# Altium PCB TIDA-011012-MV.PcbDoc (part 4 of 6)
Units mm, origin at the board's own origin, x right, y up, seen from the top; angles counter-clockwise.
Board outline 360 x 280 mm, 4 copper layers (Top Layer, Layer 1, Layer 2, Bottom Layer), stack 2.066 mm thick; 566 components, 345 nets, 1738 pads, 2486 vias.
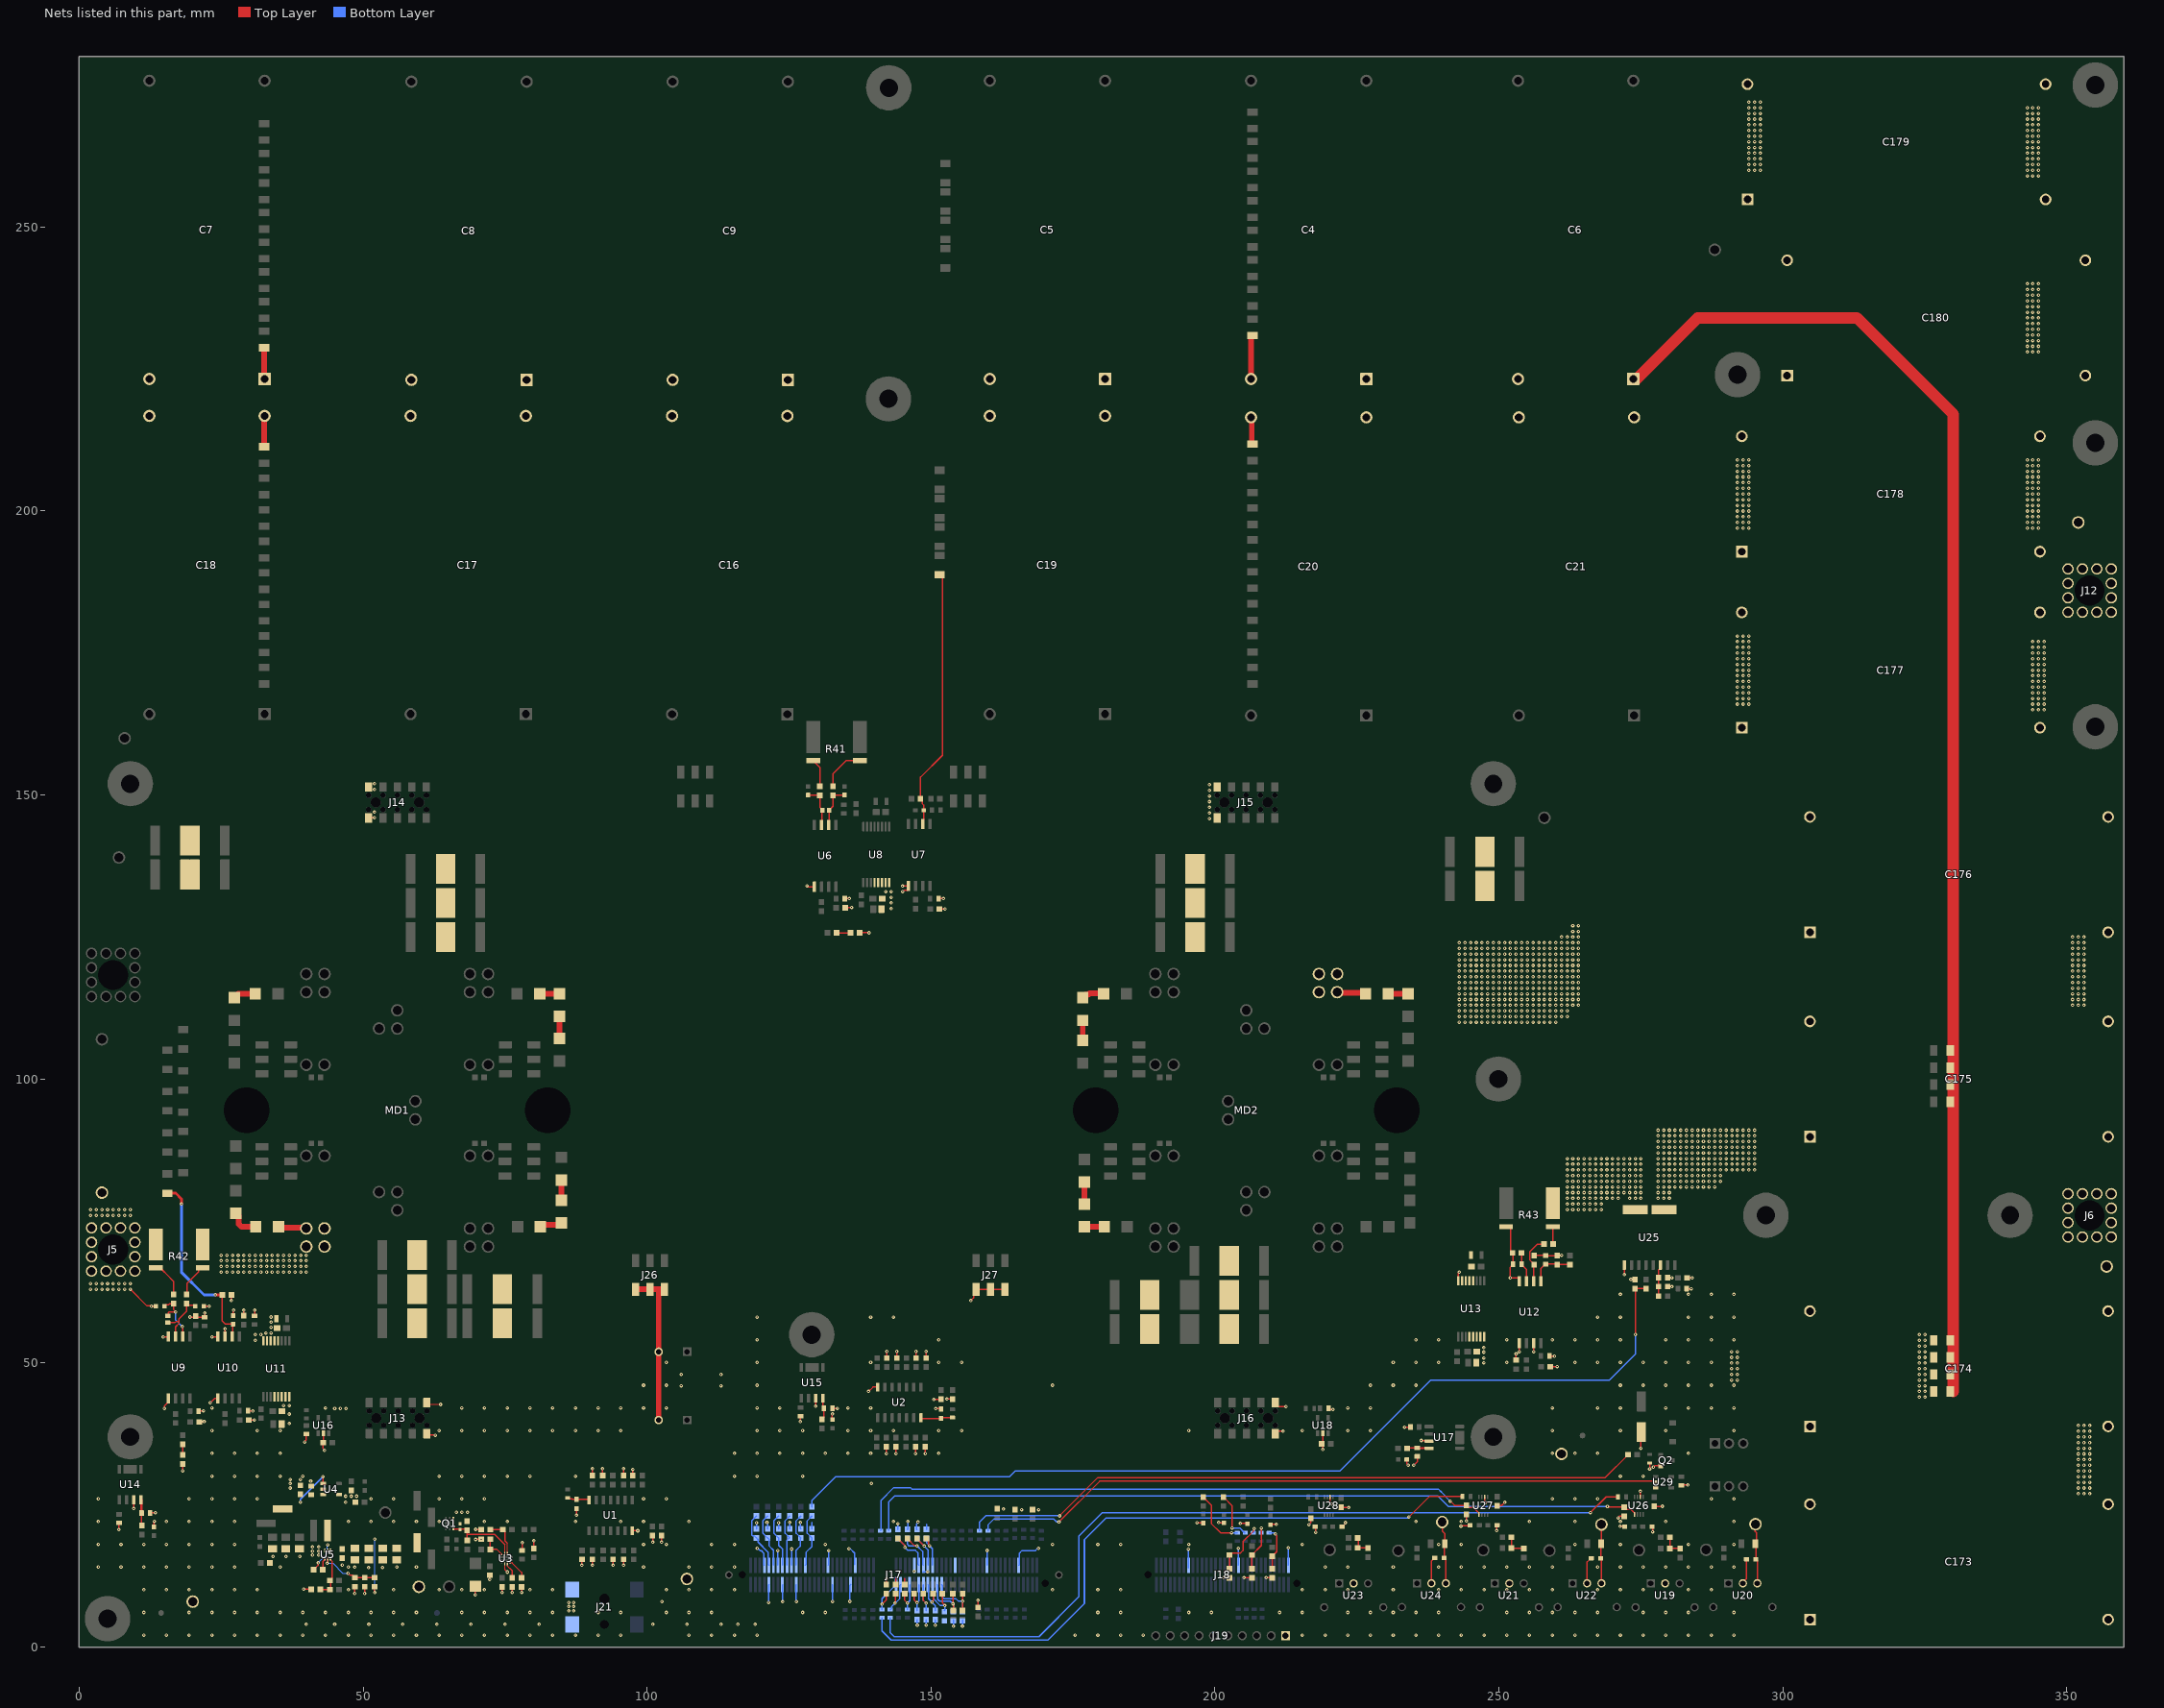
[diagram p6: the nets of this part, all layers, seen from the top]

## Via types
v1: diameter 0.6, hole 0.2, Top Layer to Bottom Layer, tented both sides, 2486 vias

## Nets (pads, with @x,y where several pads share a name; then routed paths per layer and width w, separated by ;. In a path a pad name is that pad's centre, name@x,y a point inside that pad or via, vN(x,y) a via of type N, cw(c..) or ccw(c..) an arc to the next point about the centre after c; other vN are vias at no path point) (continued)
EF_ILIM: R136.2 U3.9 | length 2.7
  Top Layer w0.2: U3.9@75.41,14.499 75.41,14.279 75.823,13.867
  Top Layer w0.254: 75.823,13.867 75.833,13.867 76.246,13.454 R136.2@76.246,12.176
EF_ITIMER: C60.1 U3.10 | length 3.7
  Top Layer w0.254: U3.10@75.86,14.824 76.21,14.824 77.897,13.137 C60.1@77.897,12.176
EF_OVLO: R138.1 R141.2 U3.2 | length 6.8
  Top Layer w0.2: U3.2@75.385,16.474 75.385,18.282
  Top Layer w0.254: R141.2@72.388,20.693 72.398,20.703 74.575,20.703 74.96,20.318 74.96,18.707 75.385,18.282
EF_PG: C62.1 Q1.3 R139.1 R142.2 U3.3 | length 13.2
  Top Layer w0.2: U3.3@74.935,16.474 74.935,18.065
  Top Layer w0.254: Q1.3@65.884,20.784 68.111,20.784 R142.2@68.321,20.574 68.321,19.824 ; R139.1@68.335,18.807 68.321,18.821 68.321,19.824 ; 74.935,18.065 73.176,19.824 68.321,19.824
EF_PGTH: R135.1 R137.2 U3.4 | length 4.2
  Top Layer w0.254: R137.2@72.386,18.961 72.386,17.183 R135.1@72.393,17.176 73.559,17.176 U3.4@74.41,16.324
FAN_EN: R88.1 R187.1 | length 120.7
  Top Layer w0.254: v1(172.619,23.095) 179.372,29.848 268.693,29.848 272.7,33.855 R187.1@272.725,33.855
  Bottom Layer w0.254: R88.1@158.514,20.444 158.514,21.978 159.63,23.095 v1(172.619,23.095)
FAN_PWM: R90.1 U29.2 | length 122.3
  Top Layer w0.254: v1(172.519,22.02) 179.699,29.2 277.07,29.2 277.078,29.192 277.419,29.192 U29.2@277.592,29.019
  Bottom Layer w0.254: R90.1@160.072,20.444 160.072,21.559 161.023,22.51 171.632,22.51 172.123,22.02 v1(172.519,22.02)
FSIRXA_CLK: R71.2 R215.1 | length 147.5
  Top Layer w0.254: v1(266.1,23.68) 268.865,26.445 R215.1@270.956,26.445
  Bottom Layer w0.254: R71.2@142.799,5.144 142.799,2.562 143.52,1.841 168.993,1.841 176,8.848 176,19.5 180.18,23.68 v1(266.1,23.68)
FSIRXA_D0: R69.2 R216.1 | length 122.2
  Top Layer w0.254: v1(234.151,22.915) 237.732,26.495 R216.1@243.555,26.495
  Bottom Layer w0.254: R69.2@141.374,5.144 141.374,2.842 142.973,1.243 143.476,1.243 143.69,1.243 144.647,1.243 170.578,1.243 177,7.665 177,18.917 180.789,22.706 233.879,22.706 234.088,22.915 v1(234.151,22.915)
FSITXA_CLK: C147.1 R72.1 U26.5 | length 138.3
  Top Layer w0.254: v1(269.089,24.735) 269.155,24.735 269.255,24.634 272.032,24.634 272.432,24.234 273.242,24.234 273.881,23.595 U26.5@273.881,23.345
  Bottom Layer w0.254: R72.1@142.521,20.494 142.521,25.519 143.627,26.625 239.186,26.625 241.077,24.735 v1(269.089,24.735)
FSITXA_D0: C149.1 R70.1 U27.5 | length 113.7
  Top Layer w0.254: v1(241.425,25.695) 242.175,24.945 C149.1@244.28,24.945 ; C149.1@244.28,24.92 244.655,24.545 245.531,24.545 246.481,23.595 U27.5@246.481,23.345
  Bottom Layer w0.2: 239.858,27.262 v1(241.425,25.695)
  Bottom Layer w0.254: R70.1@141.077,20.494 141.175,20.592 141.175,25.818 143.357,28 146.454,28 146.658,27.796 220.26,27.796 220.279,27.816 239.304,27.816 239.858,27.262
GND: C10.2 C22.2 C27.2 C28.2 C29.2 C30.2 C31.1 C32.2 C33.2 C34.2 C35.2 C36.1 C37.1 C38.1 C39.1 C40.2 C41.2 C42.1 C43.2 C44.2 C45.1 C46.2 C47.2 C48.2 C49.1 C50.1 C51.1 C52.1 C53.1 C54.2 C55.2 C56.2 C57.2 C59.2 C60.2 C61.2 C62.2 C64.2 C66.2 C67.2 C68.2 C69.2 C70.2 C72.2 C73.2 C74.2 C78.2 C81.2 C82.2 C83.2 C87.2 C88.1 C90.2 C92.2 C93.2 C97.2 C100.2 C101.2 C102.2 C106.2 C107.1 C109.2 C113.2 C114.2 C116.2 C119.1 C121.2 C122.2 C123.2 C124.1 C125.2 C126.2 C127.1 C128.2 C129.2 C130.2 C131.1 C132.2 C133.2 C135.1 C137.1 C138.1 C140.1 C141.1 C142.1 C143.1 C144.1 C145.1 C146.2 C147.2 C148.2 C149.2 C150.2 C151.2 C152.2 C153.2 C154.2 C155.2 C158.1 C159.2 C160.2 C162.2 C169.2 C170.2 C171.1 C172.2 D25.1 D26.1 D27.1 D28.1 D30.2 J13.9 J13.10 J14.9 J14.10 J15.9 J15.10 J16.9 J16.10 J17.7 J17.10 J17.13 J17.16 J17.19 J17.22 J17.35 J17.38 J17.46 J17.47 J17.65 J17.83 J17.97 J17.111 J18.135 J18.157 J18.179 J19.1 J21.2 J21.3 J26.2 J26.4 J26.6 J27.2 J27.4 J27.6 Q1.4 Q1.7 Q2.2 R53.1 R54.1 R55.1 R89.1 R91.1 R92.1 R93.1 R120.1 R121.1 R122.1 R123.1 R136.1 R137.1 R141.1 R142.1 R145.2 R146.1 R147.1 R148.1 R188.1 R190.1 R192.1 R200.1 R201.1 R203.2 R204.1 R205.1 R206.1 R207.1 TP2.1 TP21.1 TP22.1 TP23.1 U1.7 U2.7 U3.8 U4.2 U4.4 U5.3 U6.5 U7.5 U8.4 U8.5 U8.6 U8.7 U8.8 U9.5 U10.5 U11.4 U11.5 U11.6 U11.7 U11.8 U12.5 U12.7 U13.4 U13.5 U13.6 U13.7 U13.8 U14.3 U15.3 U16.2 U17.3 U18.2 U19.2 U20.2 U21.2 U22.2 U23.2 U24.2 U25.3 U26.2 U27.2 U28.2 U29.3 | length 261
  Top Layer w0.2: J13.9@61.23,43.02 61.23,42.866 61.385,42.711 v1(63.623,42.711) ; 74.935,13.665 U3.8@74.935,14.674
  Top Layer w0.254: v1(7.002,20.681) 7.002,21.843 C123.2@7.005,21.847 ; v1(9.61,24.378) 9.615,24.383 9.615,25.911 U14.3@9.62,25.916 ; C125.2@12.504,23.59 12.554,23.64 v1(13.416,23.64) ; C124.1@13.166,21.14 13.191,21.165 13.191,22.115 v1(13.216,22.14) ; v1(15,42) 15.057,42.057 15.057,42.512 15.695,43.15 U9.5@15.695,43.75 ; v1(18.235,31.021) C100.2@18.235,32.2 ; C92.2@21.051,41.547 21.101,41.597 v1(21.894,41.597) ; C93.2@21.144,39.653 21.982,39.653 v1(22,39.671) ; v1(23.075,43) 23.825,43.75 U10.5@24.395,43.75 ; C101.2@29.735,41.637 29.825,41.547 v1(30.58,41.547) ; C102.2@29.83,39.949 29.881,40 v1(30.86,40) ; R147.1@33.602,14.815 R147.1@33.64,14.852 ; v1(39.506,10.198) 40.794,10.198 R146.1@40.844,10.148 ; v1(39.7,36.1) 39.7,36.194 40,36.494 C129.2@40,37.49 ; U16.2@43,37.625 43,36.046 R190.1@42.954,36 42.954,34.949 43.204,34.699 v1(43.204,34.632) ; v1(48.529,9.423) 48.529,10.605 C172.2@48.548,10.623 ; v1(50.248,9.423) 50.248,10.596 R145.2@50.275,10.623 ; J14.9@50.97,146.18 51.15,146 51.9,146 v1@52,145.9 ; J14.10@50.97,151.62 J14.10@51,151.65 ; J13.10@61.23,37.38 62.536,37.38 62.633,37.283 v1(62.7,37.283) ; Q1.7@65.884,21.854 Q1.4@65.884,22.734 ; D30.2@69.748,10.716 69.77,10.694 v1(69.77,9.191) ; v1(69.832,18.95) 70.774,18.95 v1(70.786,18.961) R137.1@70.761,18.961 ; v1(69.85,20.722) 70.759,20.722 R141.1@70.788,20.693 ; v1(72.303,11.893) C59.2@72.303,12.643 ; v1(74.46,9.62) C61.2@74.46,10.561 ; 74.935,13.665 v1(75.4,13.2) ; v1(76.246,9.62) R136.1@76.246,10.576 ; v1(77.897,9.626) C60.2@77.897,10.576 ; C10.2@78,17 v1(78,18.38) ; C57.2@80.071,17.374 v1(80.071,18.709) ; v1(87.546,23.184) C31.1@87.546,24.359 ; v1(88.501,14.394) 88.501,15.389 R91.1@88.546,15.434 ; v1(90.392,14.394) C37.1@90.392,15.434 ; R93.1@90.392,30.209 v1(90.392,31.386) ; v1(92.158,31.386) 92.158,30.227 C39.1@92.176,30.209 ; v1(94.021,14.394) R89.1@94.021,15.434 ; v1(95.826,31.386) 95.826,30.201 C38.1@95.842,30.184 ; C36.1@95.844,15.434 95.861,15.417 v1(95.861,14.394) ; U1.7@97.356,20.484 97.366,20.475 v1(98.355,20.475) ; R92.1@97.489,30.184 v1(97.489,31.285) ; C42.1@100.962,19.632 101,19.594 v1(101,18.45) ; v1(102.546,18.45) R204.1@102.546,19.632 ; v1(126.98,39.691) 126.98,40.625 C126.2@127,40.645 ; v1(128.141,134.013) 128.208,134.013 128.358,133.863 U6.5@129.461,133.863 ; v1(129.67,42.384) 129.68,42.395 129.68,44.231 U15.3@129.691,44.241 ; v1@132.604,41.056 v1(132.614,41.045) 132.604,41.035 132.604,40.056 C127.1@132.614,40.045 ; C128.2@132.637,42.022 v1(133.513,42.022) ; C73.2@134.799,131.764 v1(135.597,131.764) ; C74.2@134.894,130.142 134.969,130.217 v1(136,130.217) ; C81.2@137.406,125.741 137.416,125.752 v1(139.079,125.752) ; v1(139,45) 139.775,45.775 U2.7@140.622,45.775 ; C153.2@142.114,11.001 142.128,11.015 v1(142.128,11.956) ; C51.1@142.117,35.275 142.136,35.256 v1(142.136,34.052) ; C49.1@142.233,50.875 v1(142.233,52.047) ; C154.2@143.764,11.016 143.771,11.022 143.771,12.052 ; v1(143.835,34.052) R122.1@143.835,35.275 ; R120.1@143.951,50.875 143.96,50.884 v1(143.96,52.047) ; v1(144.971,133.96) 145.943,133.96 145.943,133.369 145.823,133.248 145.315,133.248 145.067,133 v1(145,133) ; 145.368,12.046 145.368,10.982 C155.2@145.371,10.98 ; v1(147.247,34.052) 147.247,35.251 C52.1@147.271,35.275 ; v1(147.336,52.047) 147.336,50.926 C50.1@147.387,50.875 ; v1(148.989,34.052) R123.1@148.989,35.275 ; R121.1@149.105,50.875 v1(149.105,52.047) ; v1(150.455,43.583) 151.698,43.583 C53.1@151.773,43.658 ; v1(150.827,41.975) 151.698,41.975 C45.1@151.773,41.9 ; C82.2@151.351,131.764 v1(152.196,131.764) ; C83.2@151.446,129.933 v1(152.461,129.933) ; v1(152.788,43.658) R205.1@153.763,43.658 ; v1(157,61) 157.476,61.476 157.476,62.491 J27.2@157.96,62.975 J27.4@160.5,62.975 J27.6@163.04,62.975 ; C106.2@158.247,6.99 v1(158.247,8.222) ; v1(196.818,21.89) 197.854,21.89 D26.1@197.929,21.815 ; v1(200.648,21.915) 200.673,21.89 201.535,21.89 D25.1@201.56,21.865 ; v1(201.486,12.194) R55.1@202.541,12.194 ; v1(204.474,21.746) 205.682,21.746 D28.1@205.713,21.715 ; v1(205.098,12.191) 206.499,12.191 R54.1@206.502,12.194 ; v1(209.011,12.228) 209.8,12.228 R53.1@210.07,11.958 ; D27.1@209.753,21.546 209.803,21.596 v1(210.815,21.596) ; J16.10@210.63,37.38 210.63,37.492 211.138,38 v1(212,38) ; J16.9@210.63,42.82 211.099,42.351 212.484,42.351 v1(212.491,42.345) ; v1(216.544,21.546) 216.544,21.56 216.849,21.865 C151.2@216.849,22.665 ; C145.1@217.629,21.22 217.719,21.13 v1(217.719,20.196) ; v1(218.978,34.777) 218.978,35.971 219,35.993 U18.2@219,37.625 ; C133.2@220,42 220.175,41.825 v1(220.764,41.825) ; U28.2@220.269,26.419 220.269,25.539 220.5,25.308 v1(220.5,25.2) ; C152.2@222.221,24.61 222.285,24.545 v1(223.528,24.545) ; C137.1@222.374,21.215 222.437,21.215 222.88,21.658 222.88,21.85 v1(222.937,21.908) ; v1(233.391,38.728) 234.39,38.728 C130.2@234.417,38.755 ; C131.1@233.75,33 233.775,32.975 233.775,32.262 234,32.037 v1(234,32) ; v1(235,32) 235.616,32.616 C132.2@235.616,33.567 ; v1(236.302,36.366) 236.346,36.322 237.639,36.322 U17.3@237.683,36.278 ; U24.2@238.101,11.226 238.101,15.139 238.638,15.675 C140.1@238.701,15.675 ; v1(243.3,21.3) 243.366,21.366 244.783,21.366 C143.1@244.892,21.475 ; v1(244.28,22.213) C149.2@244.28,23.345 ; U27.2@247.481,26.445 247.481,25.6 247.615,25.466 v1(247.615,25.384) ; v1(249.599,20.49) 249.599,21.399 C144.1@249.674,21.475 ; C150.2@249.674,24.895 250.437,24.895 v1(251.007,25.466) ; C116.2@253.017,50.528 v1(253.017,51.6) ; v1(253.56,52) U12.5@253.56,53.5 ; v1(256.1,52) U12.7@256.1,53.5 ; C113.2@258.88,51.228 258.908,51.2 v1(259.774,51.2) ; C114.2@259.024,49.38 v1(260.249,49.38) ; U22.2@265.52,11.226 265.52,14.978 266.192,15.65 C138.1@266.256,15.65 ; v1(270.956,22.728) 271.262,23.034 C147.2@272.057,23.034 ; v1(271.303,21.257) 272.085,21.257 C141.1@272.131,21.21 ; v1@272,65.504 v1(272.055,65.559) U25.3@272.055,67.247 ; v1(273.235,64.725) C160.2@273.96,64.725 ; U26.2@274.881,26.445 v1(274.881,27.417) ; v1(275,35) 275,37.751 C122.2@275.075,37.826 ; v1(276.53,31.355) R188.1@276.53,32.38 ; C142.1@276.971,21.219 277.045,21.144 v1(277.045,20.282) ; v1(277.192,31.685) 277.412,31.905 Q2.2@278.471,31.905 ; C148.2@277.363,24.768 277.377,24.782 v1(278.75,24.782) ; R203.2@279.695,63.45 v1(280.445,63.45) ; C162.2@279.695,65.029 v1(280.445,65.029) ; C146.2@282.138,28.45 282.207,28.519 v1(283.288,28.519) ; C158.1@283.042,63.125 283.097,63.069 v1(283.842,63.069) ; C159.2@283.092,65 v1(284,65) ; U20.2@292.939,11.226 292.939,11.388 293.583,12.032 C135.1@293.583,15.475
  Top Layer w1: J26.2@97.96,62.975 J26.4@100.5,62.975 102,62.975 ; C56.2@102.037,39.966 102.037,62.938 102,62.975 ; J26.6@103.04,62.975 102,62.975
  Bottom Layer w0.254: C27.2@119.25,20.8 v1(119.25,21.855) ; v1(119.4,17.4) 119.469,17.4 119.916,16.953 120.125,16.953 120.524,16.554 120.524,14.517 J17.7@120.647,14.394 ; v1(121.103,21.918) 121.103,21.852 121.2,21.755 C28.2@121.2,20.8 ; v1(121.408,7.865) 121.428,7.884 121.428,10.975 J17.10@121.447,10.994 ; v1(123,17) 123.047,16.953 J17.13@123.047,14.394 ; C29.2@123.15,20.8 v1(123.15,21.852) ; J17.16@123.847,10.994 123.867,10.974 123.867,7.981 v1(123.887,7.962) ; C32.2@125.1,20.8 v1(125.1,21.918) ; J17.19@125.447,14.394 v1(125.447,17.26) ; J17.22@126.247,10.994 126.258,10.983 126.258,8.021 v1(126.268,8.01) ; v1(127,21.918) 127,20.85 C34.2@127.05,20.8 ; C40.2@129,20.8 129,21.918 ; J17.35@131.847,14.394 131.953,14.5 131.953,16.953 v1(132,17) ; v1(132.633,8.019) 132.64,8.026 132.64,10.987 J17.38@132.647,10.994 ; v1(135.547,17.307) 135.594,17.26 135.817,17.26 136.524,16.554 J17.47@136.524,14.517 ; v1(135.684,8.039) 135.731,8.086 135.731,10.864 135.724,10.871 J17.46@135.847,10.994 J17.46@135.832,11.009 ; C44.2@144.164,20.698 v1(144.164,21.721) ; C47.2@145.836,20.698 145.9,20.762 v1(145.9,22.1) ; v1(147.032,13.321) J17.65@147.04,13.329 ; C48.2@147.508,20.698 147.461,20.744 147.461,21.667 147.7,21.906 v1(147.7,22) ; C30.2@147.522,4.821 147.572,4.771 v1(147.572,3.867) ; 148.561,13.264 v1(149.416,13.264) ; v1(149.122,3.867) C33.2@149.122,4.821 ; C54.2@149.18,20.698 149.18,21.648 ; v1(150.722,3.867) C35.2@150.722,4.821 ; v1@153.922,3.867 C43.2@153.922,4.821 ; v1@155.522,3.867 C46.2@155.522,4.821 ; J17.97@159.847,14.394 v1(159.847,17.007) ; J17.111@165.455,14.386 J17.111@165.447,14.394 165.57,14.517 165.57,16.554 165.997,16.98 168.387,16.98 168.806,17.4 v1(168.9,17.4) ; J18.135@195.311,13.885 v1(195.311,17.24) 195.313,17.238 195.313,14.396 J18.135@195.315,14.394 ; v1(204.097,17.375) 204.106,17.366 204.106,14.403 J18.157@204.115,14.394 ; v1(212.902,17.469) 212.909,17.463 212.909,14.401 J18.179@212.915,14.394
  other v1: 11.371,2.096 15.371,2.096 19.37,2.096 23.37,2.096 27.37,2.096 31.37,2.096 35.37,2.096 39.37,2.096 43.37,2.096 47.37,2.096 51.37,2.096 55.37,2.096 59.37,2.096 63.37,2.096 67.37,2.096 71.37,2.096 75.37,2.096 79.37,2.096 83.37,2.096 87.37,2.096 91.37,2.096 95.37,2.096 107.37,2.096 111.37,2.096 115.37,2.096 119.37,2.096 175.37,2.096 179.37,2.096 183.37,2.096 187.37,2.096 215.37,2.096 219.37,2.096 223.37,2.096 227.37,2.096 231.37,2.096 235.37,2.096 239.37,2.096 243.37,2.096 247.37,2.096 251.37,2.096 255.37,2.096 259.37,2.096 263.37,2.096 267.37,2.096 271.37,2.096 275.37,2.096 279.37,2.096 283.37,2.096 287.37,2.096 291.37,2.096 153.922,3.667 155.522,3.667 40,4 45,4 51,4 57,4 63,4 69,4 75,4 81,4 101,4 107,4 113,4 116,4 119,4 11.371,6.096 19.37,6.096 23.37,6.096 27.37,6.096 31.37,6.096 35.37,6.096 39.37,6.096 43.37,6.096 47.37,6.096 51.37,6.096 55.37,6.096 59.37,6.096 67.37,6.096 71.37,6.096 75.37,6.096 79.37,6.096 83.37,6.096 91.37,6.096 95.37,6.096 103.37,6.096 107.37,6.096 111.37,6.096 127.37,6.096 131.37,6.096 179.37,6.096 183.37,6.096 195.37,6.096 199.37,6.096 211.37,6.096 215.37,6.096 223.37,6.096 227.37,6.096 231.37,6.096 235.37,6.096 239.37,6.096 251.37,6.096 255.37,6.096 259.37,6.096 263.37,6.096 267.37,6.096 275.37,6.096 279.37,6.096 283.37,6.096 291.37,6.096 86.205,6.364 87.046,6.364 86.201,7.123 87.046,7.123 86.201,7.839 87.046,7.839 102.6,8 11.371,10.096 15.371,10.096 19.37,10.096 23.37,10.096 27.37,10.096 31.37,10.096 47.37,10.096 55.37,10.096 63.37,10.096 67.37,10.096 71.37,10.096 79.37,10.096 83.37,10.096 103.37,10.096 107.37,10.096 111.37,10.096 115.37,10.096 171.37,10.096 179.37,10.096 183.37,10.096 215.37,10.096 219.37,10.096 223.37,10.096 231.37,10.096 239.37,10.096 243.37,10.096 247.37,10.096 251.37,10.096 255.37,10.096 259.37,10.096 267.37,10.096 271.37,10.096 275.37,10.096 283.37,10.096 287.37,10.096 50.925,13.982 53.421,14.009 48.529,14.051 55.928,14.073 3.371,14.096 7.371,14.096 11.371,14.096 15.371,14.096 19.37,14.096 23.37,14.096 27.37,14.096 35.37,14.096 47.37,14.096 59.37,14.096 99.37,14.096 107.37,14.096 111.37,14.096 115.37,14.096 219.37,14.096 223.37,14.096 231.37,14.096 239.37,14.096 243.37,14.096 247.37,14.096 251.37,14.096 255.37,14.096 259.37,14.096 267.37,14.096 271.37,14.096 275.37,14.096 279.37,14.096 283.37,14.096 287.37,14.096 291.37,14.096 46.342,14.42 34.121,15.932 36.412,15.939 38.845,15.961 41.094,16.2 42.194,16.2 41.094,16.886 42.194,16.886 41.094,17.603 42.194,17.603 3.371,18.096 7.371,18.096 11.371,18.096 15.371,18.096 19.37,18.096 23.37,18.096 27.37,18.096 99.37,18.096 103.37,18.096 111.37,18.096 115.37,18.096 131.37,18.096 171.37,18.096 179.37,18.096 183.37,18.096 195.37,18.096 215.37,18.096 239.37,18.096 243.37,18.096 263.37,18.096 271.37,18.096 283.37,18.096 291.37,18.096 3.371,22.096 15.371,22.096 19.37,22.096 23.37,22.096 27.37,22.096 47.37,22.096 51.37,22.096 55.37,22.096 59.37,22.096 63.37,22.096 71.37,22.096 75.37,22.096 87.37,22.096 95.37,22.096 99.37,22.096 107.37,22.096 143.37,22.096 235.37,22.096 243.37,22.096 255.37,22.096 263.37,22.096 271.37,22.096 279.37,22.096 291.37,22.096 66.414,23.716 67.384,23.716 68.366,23.716 165.947,24.185 168.947,24.185 162.713,24.296 46.923,25.501 3.371,26.096 19.37,26.096 23.37,26.096 27.37,26.096 31.37,26.096 51.37,26.096 55.37,26.096 63.37,26.096 67.37,26.096 71.37,26.096 99.37,26.096 103.37,26.096 259.37,26.096 263.37,26.096 267.37,26.096 287.37,26.096 291.37,26.096 46.921,26.556 47.895,26.556 48.859,26.556 37.153,28 37.153,28.765 139.5,28.8 40.769,29.186 37.153,29.496 38.943,29.496 23.37,30.096 27.37,30.096 31.37,30.096 35.37,30.096 39.37,30.096 63.37,30.096 67.37,30.096 71.37,30.096 75.37,30.096 79.37,30.096 87.37,30.096 115.37,30.096 119.37,30.096 127.37,30.096 271.37,30.096 275.37,30.096 23.37,34.096 27.37,34.096 31.37,34.096 35.37,34.096 115.37,34.096 119.37,34.096 123.37,34.096 127.37,34.096 131.37,34.096 135.37,34.096 139.37,34.096 151.37,34.096 259.37,34.096 263.37,34.096 267.37,34.096 283.37,34.096 23.37,38.096 31.37,38.096 35.37,38.096 63.37,38.096 67.37,38.096 71.37,38.096 75.37,38.096 79.37,38.096 83.37,38.096 87.37,38.096 91.37,38.096 95.37,38.096 119.37,38.096 123.37,38.096 127.37,38.096 135.37,38.096 139.37,38.096 143.37,38.096 151.37,38.096 155.37,38.096 195.37,38.096 215.37,38.096 223.37,38.096 227.37,38.096 259.37,38.096 271.37,38.096 279.37,38.096 291.37,38.096 36.975,39.346 36.975,41.021 45,42 46,42 47,42 23.37,42.096 43.37,42.096 67.37,42.096 71.37,42.096 75.37,42.096 79.37,42.096 83.37,42.096 87.37,42.096 91.37,42.096 95.37,42.096 99.37,42.096 103.37,42.096 119.37,42.096 123.37,42.096 135.37,42.096 139.37,42.096 223.37,42.096 227.37,42.096 259.37,42.096 267.37,42.096 271.37,42.096 279.37,42.096 283.37,42.096 287.37,42.096 291.37,42.096 36,42.534 36.975,42.534 324,44 325,44 324,45 325,45 106,46 113,46 324,46 325,46 99.37,46.096 103.37,46.096 119.37,46.096 171.37,46.096 227.37,46.096 231.37,46.096 235.37,46.096 271.37,46.096 275.37,46.096 279.37,46.096 283.37,46.096 287.37,46.096 291.37,46.096 290.954,47 291.954,47 324,47 325,47 106,48 113,48 290.954,48 291.954,48 324,48 325,48 290.954,49 291.954,49 324,49 325,49 290.954,50 291.954,50 324,50 325,50 247.34,50.055 103.37,50.096 119.37,50.096 139.37,50.096 151.37,50.096 155.37,50.096 231.37,50.096 235.37,50.096 239.37,50.096 251.37,50.096 263.37,50.096 267.37,50.096 271.37,50.096 275.37,50.096 279.37,50.096 283.37,50.096 287.37,50.096 247.34,50.893 290.954,51 291.954,51 324,51 325,51 247.34,51.928 290.954,52 291.954,52 324,52 325,52 247.34,52.707 324,53 325,53 324,54 325,54 119.37,54.096 151.37,54.096 235.37,54.096 239.37,54.096 251.37,54.096 259.37,54.096 263.37,54.096 267.37,54.096 271.37,54.096 279.37,54.096 283.37,54.096 287.37,54.096 291.37,54.096 324,55 325,55 119.37,58.096 139.37,58.096 143.37,58.096 267.37,58.096 271.37,58.096 283.37,58.096 287.37,58.096 291.37,58.096 271.37,62.096 283.37,62.096 287.37,62.096 291.37,62.096 143,130 143,131 143,132 142,133 143,133 199,145.834 52,146 199,146.834 52,147 199,147.834 199,148.834 199,149.834 199,150.834 52,151 199,151.834 52,152
GND_ISO_AC_SENS: C94.2 C95.2 C98.1 C99.1 C103.2 C104.2 C105.1 C108.1 C110.2 J5.1 R42.2 R179.1 TP15.1 U9.4 U10.3 U10.4 U11.12 U11.13 U11.14 U11.15 U11.16 | length 17.4
  Top Layer w0.254: v1(9,63) 11.948,60.052 12.648,60.052 v1(12.7,60) C98.1@13.5,60 ; v1(14.8,54.6) 15.645,54.6 U9.4@15.695,54.65 ; v1(19.5,58.1) 20.306,58.1 20.402,58.196 20.542,58.055 C94.2@22.1,58.055 v1(22.1,58.8) ; C99.1@21.95,60 v1(22.9,60) ; v1(23.4,54.6) 24.345,54.6 U10.4@24.395,54.65 ; U10.3@25.665,54.65 25.682,54.668 25.682,55.982 v1(25.7,56) ; v1(26.8,61) R179.1@26.8,62 ; C105.1@27.1,58.35 27.15,58.4 27.15,59.25 v1(27.2,59.3) ; C104.2@28.98,58.346 29,58.366 v1(29,59.3) ; C103.2@30.86,58.301 30.9,58.341 v1(30.9,59.3)
  other v1: 31,54 31,55 32,55 32.9,55.3 33.8,55.3 33.8,56.3 33.8,57.2 33.8,58.1 2,63 3,63 4,63 5,63 6,63 7,63 8,63 2,64 3,64 4,64 5,64 6,64 7,64 8,64 9,64 2,76 3,76 4,76 5,76 6,76 7,76 8,76 9,76 2,77 3,77 4,77 5,77 6,77 7,77 8,77 9,77
I_DC_MINUS: R41.4 R152.1 | length 5
  Top Layer w0.254: R41.4@129.231,156.068 130.446,154.853 130.446,151.595 R152.1@130.413,151.563
I_DC_POS: R41.3 R151.1 | length 7.9
  Top Layer w0.254: R151.1@132.731,151.563 132.731,153.731 135.068,156.068 R41.3@137.481,156.068
I_HALL: C160.1 R85.1 R199.2 | length 170.3
  Top Layer w0.254: v1(274,55) 274,63.085 C160.1@273.96,63.125 R199.2@275.865,63.125
  Bottom Layer w0.254: R85.1@129,24.67 129,25.818 133.182,30 163.799,30 164.799,31 222,31 238,47 269.458,47 274,51.542 v1(274,55)
I_HALL_N: R43.1 U25.2
  other v1: 262,77 263,77 264,77 265,77 266,77 267,77 268,77 262,78 263,78 264,78 265,78 266,78 267,78 268,78 262,79 263,79 264,79 265,79 266,79 267,79 268,79 269,79 270,79 271,79 273,79 274,79 275,79 262,80 263,80 264,80 265,80 266,80 267,80 268,80 269,80 270,80 271,80 272,80 273,80 274,80 275,80 262,81 263,81 264,81 265,81 266,81 267,81 268,81 269,81 270,81 271,81 272,81 273,81 274,81 275,81 262,82 263,82 264,82 265,82 266,82 267,82 268,82 269,82 270,82 271,82 272,82 273,82 274,82 275,82 262,83 263,83 264,83 265,83 266,83 267,83 268,83 269,83 270,83 271,83 272,83 273,83 274,83 275,83 262,84 263,84 264,84 265,84 266,84 267,84 268,84 269,84 270,84 271,84 272,84 273,84 274,84 275,84 262,85 263,85 264,85 265,85 266,85 267,85 268,85 269,85 270,85 271,85 272,85 273,85 274,85 275,85 262,86 263,86 264,86 265,86 266,86 267,86 268,86 269,86 270,86 271,86 272,86 273,86 274,86 275,86
I_HALL_P: C173.1 C174.1 C175.1 C176.1 U25.1
  other v1: 278,79 279,79 280,79 278,80 279,80 280,80 278,81 279,81 280,81 281,81 282,81 283,81 284,81 285,81 286,81 287,81 288,81 278,82 279,82 280,82 281,82 282,82 283,82 284,82 285,82 286,82 287,82 288,82 289,82 278,83 279,83 280,83 281,83 282,83 283,83 284,83 285,83 286,83 287,83 288,83 289,83 278,84 279,84 280,84 281,84 282,84 283,84 284,84 285,84 286,84 287,84 288,84 289,84 290,84 291,84 292,84 293,84 294,84 295,84 278,85 279,85 280,85 281,85 282,85 283,85 284,85 285,85 286,85 287,85 288,85 289,85 290,85 291,85 292,85 293,85 294,85 295,85 278,86 279,86 280,86 281,86 282,86 283,86 284,86 285,86 286,86 287,86 288,86 289,86 290,86 291,86 292,86 293,86 294,86 295,86 278,87 279,87 280,87 281,87 282,87 283,87 284,87 285,87 286,87 287,87 288,87 289,87 290,87 291,87 292,87 293,87 294,87 295,87 278,88 279,88 280,88 281,88 282,88 283,88 284,88 285,88 286,88 287,88 288,88 289,88 290,88 291,88 292,88 293,88 294,88 295,88 278,89 279,89 280,89 281,89 282,89 283,89 284,89 285,89 286,89 287,89 288,89 289,89 290,89 291,89 292,89 293,89 294,89 295,89 278,90 279,90 280,90 281,90 282,90 283,90 284,90 285,90 286,90 287,90 288,90 289,90 290,90 291,90 292,90 293,90 294,90 295,90 278,91 279,91 280,91 281,91 282,91 283,91 284,91 285,91 286,91 287,91 288,91 289,91 290,91 291,91 292,91 293,91 294,91 295,91
I_SW_NEG: C111.2 C112.2 C115.2 C117.2 C118.1 C120.2 R43.4 R184.1 U12.4 U13.12 U13.13 U13.14 U13.15 U13.16 | length 18.5
  Top Layer w0.254: U13.16@242.84,64.482 242.84,65.773 243,65.933 v1(243,66) ; R43.4@251.24,74.008 251.697,74.008 252.015,73.69 252.015,69.745 252.363,69.397 R184.1@252.382,69.397 252.49,69.289 252.49,67.295 252.222,67.027 252.149,67.027 252,66.878 v1(252,65) 253.387,65 253.56,64.827 U12.4@253.56,64.4 ; C115.2@256.213,68.927 258.219,68.927 C111.2@258.224,68.922 C112.2@260.223,68.922 260.301,69 v1(261,69)
I_SW_POS: R43.3 R182.1 | length 3.1
  Top Layer w0.254: R43.3@259.49,74.008 259.49,70.959 R182.1@259.499,70.95
IAC_NEG: R42.3 R167.1 | length 6
  Top Layer w0.254: R167.1@18.938,62.1 19,62.162 19,64.015 21.063,66.078 21.063,66.437 21.381,66.755 R42.3@21.74,66.755
IAC_POS: R42.4 R166.1 | length 6.4
  Top Layer w0.254: R42.4@13.49,66.755 14.265,66.755 16,65.02 16,65 16.6,64.4 R166.1@16.6,62.1
ID1: R47.1 R55.2 R129.2 | length 10.6
  Top Layer w0.254: R55.2@202.541,13.794 202.541,16.219 202.889,16.567 204.488,16.567 204.915,16.994 204.915,18.567 206.836,20.489 206.836,20.804 v1(206.883,20.851)
  Bottom Layer w0.254: R129.2@206.722,20.107 206.883,20.268 v1(206.883,20.851)
ID2: R46.1 R54.2 R131.2 | length 8.7
  Top Layer w0.254: R54.2@206.502,13.794 R46.1@206.502,16.194 206.502,16.219 208.172,17.889 v1(208.172,20.955)
  Bottom Layer w0.254: R131.2@208.122,20.107 208.122,20.905 v1(208.172,20.955)
ID3: R45.1 R53.2 R133.2 | length 8
  Top Layer w0.254: R53.2@210.07,13.558 R45.1@210.07,15.958 210.07,15.983 210.872,16.785 210.872,19.613 210.641,19.844 v1(210.641,19.91)
  Bottom Layer w0.254: R133.2@209.522,20.107 210.445,20.107 v1(210.641,19.91)
LED_GREEN: R48.2 R125.2 | length 10.5
  Top Layer w0.254: R48.2@197.929,26.419 197.929,26.394 199.343,24.981 199.343,21.757 200.993,20.107 v1(202.922,20.107)
  Bottom Layer w0.254: v1(202.922,20.107) R125.2@203.922,20.107
LED_RED: R49.2 R127.2 | length 8.7
  Top Layer w0.254: R49.2@201.51,26.419 201.51,26.394 203.016,24.888 v1(203.016,20.965)
  Bottom Layer w0.254: v1(203.016,20.965) 204.339,20.965 205.197,20.107 R127.2@205.322,20.107
NetC1_1: C1.1 C186.2
NetC2_2: C2.2 C181.1
NetC3_1: C3.1 C187.2
NetC4_1: C4.1 C5.1 C6.1 C7.1 C8.1 C9.1 C16.2 C17.2 C18.2 C19.2 C20.2 C21.2 R14.2 R16.2 R21.1 R22.1 R200.2 R201.2 R206.2 R207.2 R211.2 R212.2 R213.2 R214.2 | length 263.5
  Top Layer w1: R21.1@32.54,211.32 32.595,211.375 32.595,216.695 C18.2@32.65,216.75 ; R14.2@32.54,228.75 32.595,228.695 32.595,223.305 C7.1@32.65,223.25 ; C20.2@206.35,216.5 206.471,216.379 206.471,211.891 R22.1@206.592,211.77 ; C4.1@206.35,223.25 206.35,230.75 206.5,230.9 R16.2@206.592,230.9
  Top Layer w2: C6.1@273.65,223.25 273.725,223.325 274.325,223.325 285,234 313,234 330,217 330,54 330,53 330,52 330,51 330,50 330,49 330,48 330,47 330,46 R207.2@330,45
NetC11_1: C11.1 C194.2
NetC12_1: C12.1 C197.2
NetC13_1: C13.1 C196.2
NetC14_2: C14.2 C183.1
NetC15_1: C15.1 C189.2
NetC22_1: C22.1 C64.1 J23.2 U4.1 U4.3 | length 7.4
  Top Layer w0.254: v1@42.934,30 42.934,28.813 U4.1@42.982,28.765
  Bottom Layer w0.254: v1(38.943,25.501) 38.943,26.01 v1@42.934,30
  other v1: 42.9,30
NetC23_1: C23.1 C193.2
NetC24_1: C24.1 C199.2
NetC25_1: C25.1 C192.2
NetC26_2: C26.2 C184.1
NetC27_1: C27.1 J17.9 R44.2 | length 10.4
  Bottom Layer w0.254: R44.2@119.25,23.07 119.25,23.045 118.448,22.243 118.448,19.701 118.597,19.553 118.902,19.553 119.25,19.205 C27.1@119.25,19.2 119.528,18.922 119.528,18.472 121.324,16.676 121.324,14.517 J17.9@121.447,14.394
NetC28_1: C28.1 J17.11 R51.2 | length 9.8
  Bottom Layer w0.254: C28.1@121.2,19.2 121.2,19.225 120.398,20.027 120.398,22.243 121.2,23.045 R51.2@121.2,23.07 ; C28.1@121.25,19.2 121.515,18.935 121.515,17.782 122.247,17.05 J17.11@122.247,14.394
NetC29_1: C29.1 J17.15 R56.2 | length 9.6
  Bottom Layer w0.254: C29.1@123.15,19.2 123.15,19.225 122.348,20.027 122.348,22.243 123.15,23.045 R56.2@123.15,23.07 ; C29.1@123.183,19.2 123.183,17.906 123.847,17.242 J17.15@123.847,14.394
NetC30_1: C30.1 J17.68 R57.1 | length 6.5
  Top Layer w0.254: R57.1@147.033,9.394 147.033,8.284 v1(147.522,7.795)
  Bottom Layer w0.254: C30.1@147.522,6.421 v1(147.522,7.795) 147.847,8.12 J17.68@147.847,10.994
NetC31_2: C31.2 R64.2 U1.14 | length 3.9
  Top Layer w0.254: R64.2@86,26.275 86.165,26.11 86.75,26.11 86.85,26.01 C31.2@87.546,26.01 89.611,26.01 U1.14@89.736,25.884
NetC32_1: C32.1 J17.17 R67.2 | length 9.4
  Bottom Layer w0.254: J17.17@124.647,14.394 124.647,18.192 124.652,18.197 124.652,18.852 125,19.2 125,19.325 124.298,20.027 124.298,22.243 125.1,23.045 R67.2@125.1,23.07
NetC33_1: C33.1 J17.70 R68.1 | length 6.6
  Top Layer w0.254: R68.1@148.647,9.394 148.647,8.195 v1(149.122,7.72)
  Bottom Layer w0.254: J17.70@148.647,10.994 148.647,8.195 v1(149.122,7.72) C33.1@149.122,6.421
NetC34_1: C34.1 J17.21 R77.2 | length 9.7
  Bottom Layer w0.254: J17.21@126.247,14.394 126.247,17.035 126.519,17.307 126.519,17.325 127,17.806 C34.1@127,19.2 ; C34.1@127.05,19.2 127.05,19.225 126.248,20.027 126.248,22.243 127.05,23.045 R77.2@127.05,23.07
NetC35_1: C35.1 J17.72 R78.1 | length 6.7
  Top Layer w0.254: v1(150.137,7.904) 150.37,8.137 R78.1@150.37,9.394
  Bottom Layer w0.254: J17.72@149.447,10.994 149.553,10.888 149.553,8.489 150.722,7.32 C35.1@150.722,6.421
NetC40_1: C40.1 J17.25 R85.2 | length 9.8
  Bottom Layer w0.254: J17.25@127.847,14.394 127.97,14.517 127.97,16.645 129,17.675 C40.1@129,19.2 129,19.225 128.198,20.027 128.198,22.243 129,23.045 R85.2@129,23.07
NetC41_1: C41.1 J17.74 R86.1 | length 6.5
  Top Layer w0.254: R86.1@151.97,9.394 151.97,7.824 152.4,7.394 v1(152.4,7.3)
  Bottom Layer w0.254: 150.37,9.319 150.37,8.578 151.648,7.3 v1(152.4,7.3) 152.4,6.499 C41.1@152.322,6.421
NetC43_1: C43.1 J17.76 R94.1 R149.1 | length 9.8
  Top Layer w0.254: R94.1@153.839,9.369 v1(153.839,7.614) 153.839,7.548 153.922,7.464 R149.1@153.922,6.421
  Bottom Layer w0.254: J17.76@151.047,10.994 151.17,10.871 151.17,8.42 151.501,8.089 153.364,8.089 153.922,7.531 C43.1@153.922,6.421
NetC44_1: C44.1 J17.67 R97.2 | length 9.1
  Top Layer w0.254: R97.2@144.164,19.098 144.164,19.073 145.352,17.884 145.352,17.598 v1(145.4,17.551)
  Bottom Layer w0.254: C44.1@144.164,19.098 144.164,19.073 144.512,18.725 144.537,18.725 145.352,17.909 145.352,17.598 145.922,17.029 147.249,17.029 147.724,16.554 147.724,14.517 J17.67@147.847,14.394
NetC45_2: C45.2 R104.2 U2.14 | length 5.6
  Top Layer w0.254: U2.14@148.242,40.375 148.367,40.249 C45.2@151.773,40.249 151.923,40.4 R104.2@153.763,40.4
NetC46_1: C46.1 J17.78 R109.1 R150.1 | length 10.8
  Top Layer w0.254: R150.1@155.522,6.421 155.572,6.471 v1(155.572,8.051) R109.1@155.572,9.369
  Bottom Layer w0.254: J17.78@151.847,10.994 151.97,10.871 151.97,8.835 152.262,8.543 154.359,8.543 154.851,8.051 v1(155.572,8.051) 155.572,6.471 C46.1@155.522,6.421
NetC47_1: C47.1 J17.69 R110.2 | length 9
  Top Layer w0.254: R110.2@145.836,19.098 145.836,19.073 147.046,17.863 147.498,17.863 v1(147.545,17.815)
  Bottom Layer w0.254: C47.1@145.836,19.098 145.836,18.084 146.104,17.815 v1(147.545,17.815) 148.524,16.836 148.524,14.517 J17.69@148.647,14.394
NetC48_1: C48.1 J17.71 R113.2 | length 7.3
  Top Layer w0.254: R113.2@147.508,19.098 147.508,19.073 v1(148.791,17.789)
  Bottom Layer w0.254: C48.1@147.508,19.098 147.508,19.073 v1(148.791,17.789) 149.447,17.133 J17.71@149.447,14.394
NetC54_1: C54.1 J17.73 R124.2 | length 6.6
  Top Layer w0.254: R124.2@149.18,19.098 149.528,18.75 149.528,18.093 149.718,17.903 v1(149.718,17.836)
  Bottom Layer w0.254: C54.1@149.18,19.098 149.189,19.088 149.189,18.365 150.247,17.307 J17.73@150.247,14.394
NetC58_1: C58.1 U5.4 | length 2.1
  Top Layer w0.254: C58.1@42.909,13.62 42.926,13.637 42.926,15.043 43.259,15.376 U5.4@43.259,15.561
NetC58_2: C58.2 L7.1 U5.2 | length 5.4
  Top Layer w0.254: C58.2@41.309,13.62 41.334,13.62 41.709,13.995 41.709,14.02 42.109,14.42 v1(42.109,14.815)
  Bottom Layer w0.2: v1(42.109,14.815) 43.707,16.414 43.707,17.933 v1(43.784,18.01)
NetC63_2: C63.2 R144.1 R146.2 U5.6 | length 7.4
  Top Layer w0.254: R146.2@42.444,10.148 44.119,10.148 R144.1@44.143,10.123 44.259,10.239 C63.2@44.259,11.748 ; C63.2@44.143,11.748 44.5,12.105 44.5,15.135 44.259,15.376 U5.6@44.259,15.561
NetC65_1: C65.1 C191.2
NetC70_1: C70.1 C72.1 C169.1 C170.1 C171.2 J22.2 R143.2 U5.1 | length 10.5
  Top Layer w0.254: R143.2@52.016,10.623 52.016,9.578 v1(52.025,9.569)
  Bottom Layer w0.2: v1(52.025,9.569) v1(52.025,19)
NetC71_1: C71.1 C195.2
NetC77_1: C77.1 C80.2 R152.2 U6.3 | length 7.5
  Top Layer w0.254: C80.2@128.366,150.013 130.363,150.013 R152.2@130.413,149.963 130.413,147.858 130.883,147.388 C77.1@130.883,147.313 130.807,147.237 130.807,144.839 U6.3@130.731,144.763
NetC77_2: C77.2 C79.2 R151.2 U6.2 | length 7.5
  Top Layer w0.254: U6.2@132.001,144.763 132.042,144.804 132.042,147.272 C77.2@132.083,147.313 ; C77.2@132.083,147.388 132.731,148.036 R151.2@132.731,149.963 132.781,150.013 C79.2@134.749,150.013
NetC81_1: C81.1 R154.1 | length 2.4
  Top Layer w0.254: R154.1@133.366,125.743 133.368,125.741 C81.1@135.806,125.741
NetC86_2: C86.2 R162.2 R164.2 U7.2 | length 47.3
  Top Layer w0.254: R164.2@148.127,149.343 R164.2@148.152,149.343 ; U7.2@148.536,144.913 148.536,145.513 148.736,145.713 C86.2@148.736,147.313 148.736,148.187 148.5,148.422 148.5,148.995 R164.2@148.152,149.343 ; R162.2@151,189 151.498,189 R162.2@151.599,188.899 ; R162.2@151.5,188.8 151.8,188.8 152,189 152,157 148.152,153.152 R164.2@148.152,149.343
NetC96_1: C96.1 C99.2 R167.2 U9.3 | length 10.5
  Top Layer w0.254: C96.1@15.6,57.1 16.835,57.1 17.072,57.337 17.6,57.337 ; U9.3@16.965,54.65 16.965,56.365 17.6,57 17.6,57.337 ; R167.2@18.938,60.5 R167.2@18.938,60.475 ; C99.2@20.45,60 20.25,60.2 19.213,60.2 R167.2@18.938,60.475 ; 17.6,57.337 17.6,57.813 18.938,59.151 R167.2@18.938,60.475
NetC96_2: C96.2 C98.2 R166.2 U9.2 | length 10.3
  Top Layer w0.254: C98.2@15,60 15.248,60.248 15.748,60.248 15.9,60.4 16.5,60.4 R166.2@16.6,60.5 16.6,59.467 17,59.067 v1(17,59) 15.849,59 15.7,58.851 15.7,58.4 C96.2@15.6,58.3 ; v1(18.162,56.42) 18.198,56.384 18.198,54.687 U9.2@18.235,54.65
  Bottom Layer w0.254: v1(17,59) 17,57.582 v1(18.162,56.42)
NetC100_1: C100.1 R169.1 | length 1.9
  Top Layer w0.254: C100.1@18.235,33.8 R169.1@18.235,35.721
NetC105_2: C105.2 R177.2 R179.2 U10.2 | length 33.7
  Top Layer w0.254: R179.2@25.2,62 25.2,57.4 25.75,56.85 C105.2@27.1,56.85 27.017,56.767 27.017,54.733 U10.2@26.935,54.65
  Top Layer w0.5: R177.2@15.5,79.9 17,79.9 18,78.9 v1(18,78) ; v1(24,62) R179.2@25.2,62
  Bottom Layer w0.5: v1(18,78) 18,66 22,62 v1(24,62)
NetC111_1: C111.1 C112.1 R181.2 U12.1 | length 7.7
  Top Layer w0.254: U12.1@257.37,64.4 257.37,66.662 258.119,67.412 C111.1@258.224,67.412 260.133,67.412 C112.1@260.223,67.322 R181.2@262.5,67.322
NetC115_1: C115.1 R182.2 U12.2 | length 8.6
  Top Layer w0.254: U12.2@256.1,64.4 256.1,67.213 C115.1@256.213,67.327 256.213,67.352 255.411,68.154 255.411,69.562 256.799,70.95 R182.2@257.899,70.95
NetC117_1: C117.1 R184.2 U12.3 | length 5.2
  Top Layer w0.254: R184.2@253.982,69.397 254,69.379 C117.1@254,67.4 ; C117.1@254,67.295 254.83,66.465 U12.3@254.83,64.4
NetC125_1: C125.1 R186.2 U14.4 | length 7
  Top Layer w0.254: U14.4@10.89,25.916 10.89,23.695 C125.1@10.994,23.59 ; R186.2@11.016,21.39 10.994,21.413 C125.1@10.994,23.59 ; U14.4@11.016,26.012 11.005,26 11.005,23.602 C125.1@10.994,23.59
NetC128_1: C128.1 R189.2 U15.4 | length 5
  Top Layer w0.254: R189.2@130.81,40.11 131.127,40.426 C128.1@131.127,42.022 131.055,42.093 130.984,42.165 130.984,44.354 130.984,43.854 U15.4@130.961,43.831
NetC132_1: C132.1 R191.2 U17.4 | length 4.5
  Top Layer w0.254: R191.2@233.8,35 233.877,35.077 C132.1@235.616,35.077 235.679,35.014 236.212,35.014 ; 236.779,35.037 236.756,35.014 236.212,35.014 ; U17.4@237.683,35.008 237.649,35.042 236.24,35.042 236.212,35.014
NetC134_1: C134.1 R193.2 R194.1 | length 3.9
  Top Layer w0.254: R193.2@280.1,19.35 280.1,17.425 C134.1@280.1,17.35 280.175,17.425 281.817,17.425 R194.1@281.917,17.325
NetC135_2: C135.2 L1.2 TP5.1 U20.3 | length 10.7
  Top Layer w0.254: TP5.1@295.158,21.641 295.105,21.588 295.105,20.34 295.308,20.136 295.308,18.425 295.158,18.275 295.234,18.199 C135.2@295.234,15.475 295.479,15.23 U20.3@295.479,11.226
NetC136_1: C136.1 R196.2 R197.1 | length 4.1
  Top Layer w0.254: R196.2@252.204,19.325 C136.1@252.204,17.425 254.294,17.425 R197.1@254.369,17.35
NetC138_2: C138.2 L2.2 TP8.1 U22.3 | length 10.5
  Top Layer w0.254: U22.3@268.06,11.226 268.06,15.496 C138.2@267.906,15.65 267.906,18.049 L2.2@268.02,18.162 268.06,18.202 TP8.1@268.06,21.578
NetC139_1: C139.1 R208.2 R209.1 | length 3.7
  Top Layer w0.254: C139.1@225.128,19.212 225.203,19.212 225.203,17.538 R208.2@225.128,17.463 226.897,17.463 R209.1@226.951,17.409
NetC140_2: C140.2 L3.2 TP11.1 U24.3 | length 11.1
  Top Layer w0.254: TP11.1@240,22 240,20.44 240.466,19.974 L3.2@240.466,18.159 240.352,18.045 C140.2@240.352,15.675 ; C140.2@240.36,15.675 240.641,15.394 U24.3@240.641,11.226
NetC153_1: C153.1 J17.58 R69.1 | length 7.8
  Top Layer w0.254: v1(141.374,7.558) 142.114,8.298 C153.1@142.114,9.401
  Bottom Layer w0.254: R69.1@141.374,6.594 141.374,8.521 143.365,10.512 143.724,10.512 143.847,10.635 J17.58@143.847,10.994
NetC154_1: C154.1 J17.60 R71.1 | length 6.9
  Top Layer w0.254: v1(143.672,7.72) 143.764,7.812 C154.1@143.764,9.416
  Bottom Layer w0.254: R71.1@142.799,6.594 142.863,6.594 143.061,6.792 143.061,7.109 144.524,8.572 144.524,10.871 J17.60@144.647,10.994
NetC155_1: C155.1 J17.64 R74.1 | length 6.4
  Top Layer w0.254: C155.1@145.371,9.38 145.371,8.215 v1(145.836,7.75)
  Bottom Layer w0.254: R74.1@145.836,6.594 v1(145.836,7.75) 146.247,8.162 J17.64@146.247,10.994
NetC161_1: C161.1 C165.2
NetC162_1: C162.1 R202.2 R203.1 U25.8 | length 5.6
  Top Layer w0.254: R202.2@278.095,61.775 278.095,66.412 278.405,66.722 U25.8@278.405,67.247
NetC163_1: C163.1 C190.2
NetC164_1: C164.1 C198.2
NetC166_1: C166.1 C185.2
NetC167_1: C167.1 C188.2
NetC168_2: C168.2 C182.1
NetC172_1: C172.1 R143.1 R145.1 U5.5 | length 10.2
  Top Layer w0.254: v1(43.669,14.73) 43.669,14.824 43.781,14.936 43.781,15.539 U5.5@43.759,15.561 ; v1(47.351,13.003) 47.739,12.614 48.173,12.614 C172.1@48.548,12.239 ; C172.1@48.548,12.223 R145.1@50.248,12.223 ; R145.1@50.275,12.223 R143.1@52.016,12.223
  Bottom Layer w0.2: v1(43.669,14.73) 44.686,14.73 46.414,13.003 v1(47.351,13.003)
NetC173_2: C173.2 C174.2 C175.2 C176.2 J6.1 TP16.1
  other v1: 352,27 353,27 354,27 352,28 353,28 354,28 352,29 353,29 354,29 352,30 353,30 354,30 352,31 353,31 354,31 352,32 353,32 354,32 352,33 353,33 354,33 352,34 353,34 354,34 352,35 353,35 354,35 352,36 353,36 354,36 352,37 353,37 354,37 352,38 353,38 354,38 352,39 353,39 354,39 351,113 352,113 353,113 351,114 352,114 353,114 351,115 352,115 353,115 351,116 352,116 353,116 351,117 352,117 353,117 351,118 352,118 353,118 351,119 352,119 353,119 351,120 352,120 353,120 351,121 352,121 353,121 351,122 352,122 353,122 351,123 352,123 353,123 351,124 352,124 353,124 351,125 352,125 353,125
NetC177_1: C177.1 C178.1 C179.1 C180.1 D15.1 MD2.AC1 | length 5.1
  Top Layer w1: MD2.AC1@221.5,115.2 221.538,115.162 226.362,115.162 D15.1@226.5,115.023
  other v1: 243,110 244,110 245,110 246,110 247,110 248,110 249,110 250,110 251,110 252,110 253,110 254,110 255,110 256,110 257,110 258,110 259,110 260,110 243,111 244,111 245,111 246,111 247,111 248,111 249,111 250,111 251,111 252,111 253,111 254,111 255,111 256,111 257,111 258,111 259,111 260,111 261,111 262,111 243,112 244,112 245,112 246,112 247,112 248,112 249,112 250,112 251,112 252,112 253,112 254,112 255,112 256,112 257,112 258,112 259,112 260,112 261,112 262,112 243,113 244,113 245,113 246,113 247,113 248,113 249,113 250,113 251,113 252,113 253,113 254,113 255,113 256,113 257,113 258,113 259,113 260,113 261,113 262,113 263,113 264,113 243,114 244,114 245,114 246,114 247,114 248,114 249,114 250,114 251,114 252,114 253,114 254,114 255,114 256,114 257,114 258,114 259,114 260,114 261,114 262,114 263,114 264,114 243,115 244,115 245,115 246,115 247,115 248,115 249,115 250,115 251,115 252,115 253,115 254,115 255,115 256,115 257,115 258,115 259,115 260,115 261,115 262,115 263,115 264,115 243,116 244,116 245,116 246,116 247,116 248,116 249,116 250,116 251,116 252,116 253,116 254,116 255,116 256,116 257,116 258,116 259,116 260,116 261,116 262,116 263,116 264,116 243,117 244,117 245,117 246,117 247,117 248,117 249,117 250,117 251,117 252,117 253,117 254,117 255,117 256,117 257,117 258,117 259,117 260,117 261,117 262,117 263,117 264,117 243,118 244,118 245,118 246,118 247,118 248,118 249,118 250,118 251,118 252,118 253,118 254,118 255,118 256,118 257,118 258,118 259,118 260,118 261,118 262,118 263,118 264,118 243,119 244,119 245,119 246,119 247,119 248,119 249,119 250,119 251,119 252,119 253,119 254,119 255,119 256,119 257,119 258,119 259,119 260,119 261,119 262,119 263,119 264,119 243,120 244,120 245,120 246,120 247,120 248,120 249,120 250,120 251,120 252,120 253,120 254,120 255,120 256,120 257,120 258,120 259,120 260,120 261,120 262,120 263,120 264,120 243,121 244,121 245,121 246,121 247,121 248,121 249,121 250,121 251,121 252,121 253,121 254,121 255,121 256,121 257,121 258,121 259,121 260,121 261,121 262,121 263,121 264,121 243,122 244,122 245,122 246,122 247,122 248,122 249,122 250,122 251,122 252,122 253,122 254,122 255,122 256,122 257,122 258,122 259,122 260,122 261,122 262,122 263,122 264,122 243,123 244,123 245,123 246,123 247,123 248,123 249,123 250,123 251,123 252,123 253,123 254,123 255,123 256,123 257,123 258,123 259,123 260,123 261,123 262,123 263,123 264,123 243,124 244,124 245,124 246,124 247,124 248,124 249,124 250,124 251,124 252,124 253,124 254,124 255,124 256,124 257,124 258,124 259,124 260,124 261,124 262,124 263,124 264,124 261,125 262,125 263,125 264,125 263,126 264,126 263,127 264,127 292,166 293,166 294,166 292,167 293,167 294,167 292,168 293,168 294,168 292,169 293,169 294,169 292,170 293,170 294,170 292,171 293,171 294,171 292,172 293,172 294,172 292,173 293,173 294,173 292,174 293,174 294,174 292,175 293,175 294,175 292,176 293,176 294,176 292,177 293,177 294,177 292,178 293,178 294,178 292,197 293,197 294,197 292,198 293,198 294,198 292,199 293,199 294,199 292,200 293,200 294,200 292,201 293,201 294,201 292,202 293,202 294,202 292,203 293,203 294,203 292,204 293,204 294,204 292,205 293,205 294,205 292,206 293,206 294,206 292,207 293,207 294,207 292,208 293,208 294,208 292,209 293,209 294,209 294,260 295,260 296,260 294,261 295,261 296,261 294,262 295,262 296,262 294,263 295,263 296,263 294,264 295,264 296,264 294,265 295,265 296,265 294,266 295,266 296,266 294,267 295,267 296,267 294,268 295,268 296,268 294,269 295,269 296,269 294,270 295,270 296,270 294,271 295,271 296,271 294,272 295,272 296,272
NetC177_2: C177.2 C178.2 C179.2 C180.2 J12.1 TP20.1
  other v1: 344,165 345,165 346,165 344,166 345,166 346,166 344,167 345,167 346,167 344,168 345,168 346,168 344,169 345,169 346,169 344,170 345,170 346,170 344,171 345,171 346,171 344,172 345,172 346,172 344,173 345,173 346,173 344,174 345,174 346,174 344,175 345,175 346,175 344,176 345,176 346,176 344,177 345,177 346,177 343,197 344,197 345,197 343,198 344,198 345,198 343,199 344,199 345,199 343,200 344,200 345,200 343,201 344,201 345,201 343,202 344,202 345,202 343,203 344,203 345,203 343,204 344,204 345,204 343,205 344,205 345,205 343,206 344,206 345,206 343,207 344,207 345,207 343,208 344,208 345,208 343,209 344,209 345,209 343,228 344,228 345,228 343,229 344,229 345,229 343,230 344,230 345,230 343,231 344,231 345,231 343,232 344,232 345,232 343,233 344,233 345,233 343,234 344,234 345,234 343,235 344,235 345,235 343,236 344,236 345,236 343,237 344,237 345,237 343,238 344,238 345,238 343,239 344,239 345,239 343,240 344,240 345,240 343,259 344,259 345,259 343,260 344,260 345,260 343,261 344,261 345,261 343,262 344,262 345,262 343,263 344,263 345,263 343,264 344,264 345,264 343,265 344,265 345,265 343,266 344,266 345,266 343,267 344,267 345,267 343,268 344,268 345,268 343,269 344,269 345,269 343,270 344,270 345,270 343,271 344,271 345,271
NetD1_2: D1.2 D5.1 | length 3.8
  Top Layer w1: D1.2@81.3,74.2 81.439,74.339 84.561,74.339 D5.1@84.9,74.677
NetD2_2: D2.2 D6.1 | length 3.7
  Top Layer w1: D2.2@81,115.2 81.177,115.023 D6.1@84.6,115.023
NetD3_2: D3.2 D7.1 | length 4.1
  Top Layer w1: D7.1@176.7,114.323 177.2,114.823 177.623,114.823 177.9,115.1 D3.2@180.5,115.1
NetD4_2: D4.2 D8.1 | length 3.6
  Top Layer w1: D8.1@177,73.977 D4.2@180.5,73.977 180.523,73.977 D4.2@180.6,73.9
NetD5_2: D5.2 D9.1 | length 3.7
  Top Layer w1: D5.2@84.9,78.5 D5.2@84.9,78.677 D9.1@84.9,82.214
NetD6_2: D6.2 D10.1 | length 3.7
  Top Layer w1: D10.1@84.6,107.16 D6.2@84.6,110.9
NetD7_2: D7.2 D11.1 | length 3.8
  Top Layer w1: D11.1@176.7,106.786 D7.2@176.7,110.323 D7.2@176.7,110.6
NetD8_2: D8.2 D12.1 | length 3.9
  Top Layer w1: D8.2@176.9,78 177,78.1 D12.1@177,81.84
NetD13_1: D13.1 MD1.AC1 R42.1 | length 5
  Top Layer w1: D13.1@35.1,73.977 35.238,73.838 39.838,73.838 MD1.AC1@40,74
  other v1: 25,66 26,66 27,66 28,66 29,66 30,66 31,66 32,66 33,66 34,66 35,66 36,66 37,66 38,66 39,66 40,66 25,67 26,67 27,67 28,67 29,67 30,67 31,67 32,67 33,67 34,67 35,67 36,67 37,67 38,67 39,67 40,67 25,68 26,68 27,68 28,68 29,68 30,68 31,68 32,68 33,68 34,68 35,68 36,68 37,68 38,68 39,68 40,68 25,69 26,69 27,69 28,69 29,69 30,69 31,69 32,69 33,69 34,69 35,69 36,69 37,69 38,69 39,69 40,69
NetD13_2: D13.2 D17.1 | length 4.8
  Top Layer w1: D17.1@28,76 28.105,75.895 28.105,74.458 28.586,73.977 D13.2@31.1,73.977
NetD14_2: D14.2 D18.1 | length 4
  Top Layer w1: D18.1@27.3,114.323 27.977,115 D14.2@31,115
NetD15_2: D15.2 D19.1 | length 3.5
  Top Layer w1: D15.2@230.5,115 230.523,115.023 D19.1@234,115.023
